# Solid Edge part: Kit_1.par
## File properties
Sűrűség: 0,000 kg/m^3
Pontosság: 0,990
Author: bmolnar
Last saved by: bmolnar
Revision: 77
Username: bmolnar
Dokumentum tartalom típus: 0
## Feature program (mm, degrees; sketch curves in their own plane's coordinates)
base feature "unnamed BaseFeature 1"
sketch for "unnamed Cutout 1" plane through (0, 0.0012, 84.75) normal (0, 0, -1) x-axis (-1, 0, 0)
  circle centre (0, -0.0012) radius 6
extrude "unnamed Cutout 1" cut through along -normal
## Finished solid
Body 1: solid body, 46 faces, 63 edges, 49 vertices, 1 internal void.
  Faces by surface: cylinder 16, cone 14, plane 12, torus 4
  Edges by curve: circle 49, line 14
Bounding box of the edges (mm; curved faces can reach further): 44.500 x 44.124 x 10.750, from (-22.2144, -20.85, 84.75) to (22.2856, 23.2744, 95.5).
Cylindrical faces by radius (mm): R1.25 x2, R2.5 x4, R6 x1, R6.27 x1, R6.85 x1, R7 x1, R8.16 x1, R8.25 x1, R14 x1, R19.175 x1, R20.85 x1, R22.25 x1
Conical faces (half-angle, radius in mm at the cone's reference point): 3 deg R8.205 x1, 7 deg R7.5925 x1, 14 deg R6.135 x1, 14 deg R6.4811 x1, 17 deg R6.135 x1, 23 deg R6.829 x1, 42.5 deg R6.1233 x1, 45 deg R7.1 x1, 45 deg R7.15 x1, 45 deg R13.5 x1, 84 deg R59.397 x2, 85 deg R7.9463 x1, 87 deg R6.1765 x1
Toroidal faces (ring radius, tube radius in mm): R6.8057 r0.2025 x1, R7.2522 r0.2925 x1, R7.96 r0.2 x1, R14.8 r0.8 x1
Planar faces by outward normal: +z 7, -z 3, oblique 2
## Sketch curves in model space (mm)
circle centre (0, 0, 84.75) radius 6
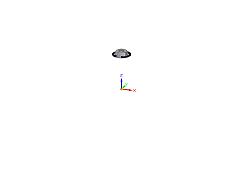
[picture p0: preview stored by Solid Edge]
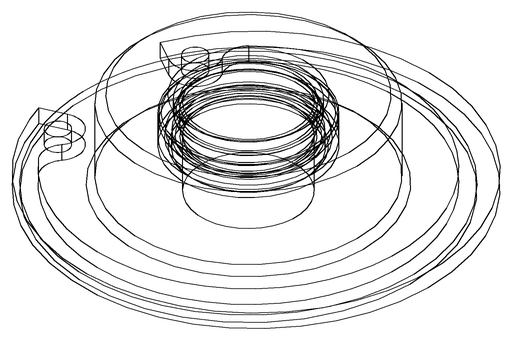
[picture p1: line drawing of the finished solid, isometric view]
